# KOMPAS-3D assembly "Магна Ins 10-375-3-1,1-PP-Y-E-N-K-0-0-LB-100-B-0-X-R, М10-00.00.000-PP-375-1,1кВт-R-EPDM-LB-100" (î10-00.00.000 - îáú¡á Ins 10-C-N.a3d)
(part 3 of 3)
- Part/product: Магна Ins 10-PP-425-0,55кВт  | designation М10-00.00.000-PP-425-0,55кВт
    Материал: Полипропилен  ГОСТ 26996-86 (density 900 kg/m3)
    Масса: 11.5823
  - Component [detail]: Втулка ответная  | designation М10А-00.00.003-01  | pos. 6  | Масса: 0.031838; Раздел спецификации: Детали; Форматы листов документа: A4; Примечание: Заим.; source file: D:\AquaProf\АкваProf 190\3Д модель\..\..\..\Magna\Магна Ins\Магна ins 10\М10-00.00.000\3Д\М10А-00.00.003-01 - Втулка ответная.cdw, D:\AquaProf\АкваProf 190\3Д модель\М10А-00.00.003 - Втулка ответная.m3d
  - Component [detail]: Защитная втулка  | designation М10-00.00.003  | pos. 5  | Масса: 0.0193569; Раздел спецификации: Детали; Форматы листов документа: A4; source file: D:\Magna\Магна Ins\Магна ins 10\М10-00.00.000\3Д\М10-00.00.003 - Защитная втулка.cdw, М10-00.00.003 - Защитная втулка.m3d
  - Component [detail]: Импеллер Магна10  | designation М10-00.00.001  | pos. 3  | Масса: 0.169927; Раздел спецификации: Детали; Форматы листов документа: A3; source file: М10-00.00.001 - Импеллер Магна10.cdw, М10-00.00.001 - Импеллер Магна10.m3d
  - Component [detail]: Крышка  | designation М10-00.00.002  | pos. 4
      Материал: Полипропилен  ГОСТ 26996-86 (density 900 kg/m3)
      Масса: 0.324102
      Раздел спецификации: Детали
      Форматы листов документа: 4xA4
      Примечание: @100~)4xA4
      source file: М10-00.00.002 - Крышка.cdw, М10-00.00.002 - Крышка.m3d
  - Component [assembly]: Вал  | designation М10-00.15.000-0,55кВт-425  | pos. 1
      Материал: Полипропилен  ГОСТ 26996-86 (density 900 kg/m3)
      Масса: 0.580892
      Раздел спецификации: Сборочные единицы
      Форматы листов документа: 2xA3
      Примечание: @100~)2xA3
      source file: М10-00.15.000 - Вал.a3d
  - Component [assembly]: Корпус полипропилен 425 0,55кВт  | designation М10-00.20.000-PP-425-0,55кВт  | pos. 2  | Материал: Полипропилен  ГОСТ 26996-86 (density 900 kg/m3); Масса: 5.21242; Раздел спецификации: Сборочные единицы; Форматы листов документа: 3xA3; Примечание: @100~)3xA3@101~)3xA3
- Part/product: Магна Ins 10-425-3-0,55-PP-Y-E-N-K-0-0-L-0-B-0-X-M  | designation М10-00.00.000-PP-425-0,55кВт-M-EPDM
    Материал: Полипропилен  ГОСТ 26996-86 (density 900 kg/m3)
    Масса: 12.5317
  - Component [assembly]: Корпус полипропилен 425 0,55кВт  / с разъёмной муфтой  | designation М10-00.20.000-PP-425-0,55кВт-M  | pos. 2  | Материал: Полипропилен  ГОСТ 26996-86 (density 900 kg/m3); Масса: 6.1618; Раздел спецификации: Сборочные единицы; Форматы листов документа: 3xA3; Примечание: @100~)3xA3@101~)3xA3
  - Component [assembly]: Вал  | designation М10-00.15.000-0,55кВт-425  | pos. 1
      Материал: Полипропилен  ГОСТ 26996-86 (density 900 kg/m3)
      Масса: 0.580892
      Раздел спецификации: Сборочные единицы
      Форматы листов документа: 2xA3
      Примечание: @100~)2xA3
      source file: М10-00.15.000 - Вал.a3d
  - Component [detail]: Крышка  | designation М10-00.00.002  | pos. 4
      Материал: Полипропилен  ГОСТ 26996-86 (density 900 kg/m3)
      Масса: 0.324102
      Раздел спецификации: Детали
      Форматы листов документа: 4xA4
      Примечание: @100~)4xA4
      source file: М10-00.00.002 - Крышка.cdw, М10-00.00.002 - Крышка.m3d
  - Component [detail]: Импеллер Магна10  | designation М10-00.00.001  | pos. 3  | Масса: 0.169927; Раздел спецификации: Детали; Форматы листов документа: A3; source file: М10-00.00.001 - Импеллер Магна10.cdw, М10-00.00.001 - Импеллер Магна10.m3d
  - Component [detail]: Защитная втулка  | designation М10-00.00.003  | pos. 5  | Масса: 0.0193569; Раздел спецификации: Детали; Форматы листов документа: A4; source file: D:\Magna\Магна Ins\Магна ins 10\М10-00.00.000\3Д\М10-00.00.003 - Защитная втулка.cdw, М10-00.00.003 - Защитная втулка.m3d
  - Component [detail]: Втулка ответная  | designation М10А-00.00.003-01  | pos. 6  | Масса: 0.031838; Раздел спецификации: Детали; Форматы листов документа: A4; Примечание: Заим.; source file: D:\AquaProf\АкваProf 190\3Д модель\..\..\..\Magna\Магна Ins\Магна ins 10\М10-00.00.000\3Д\М10А-00.00.003-01 - Втулка ответная.cdw, D:\AquaProf\АкваProf 190\3Д модель\М10А-00.00.003 - Втулка ответная.m3d
- Part/product: Магна Ins 10-425-3-0,55-PP-Y-E-N-K-0-0-L-0-B-0-X-R  | designation М10-00.00.000-PP-425-0,55кВт-R-EPDM
    Материал: Полипропилен  ГОСТ 26996-86 (density 900 kg/m3)
    Масса: 11.6152
  - Component [assembly]: Корпус полипропилен 425 0,55кВт  / с резьбовым переходником  | designation М10-00.20.000-PP-425-0,55кВт-R  | pos. 2  | Материал: Полипропилен  ГОСТ 26996-86 (density 900 kg/m3); Масса: 5.24529; Раздел спецификации: Сборочные единицы; Форматы листов документа: 3xA3; Примечание: @100~)3xA3@101~)3xA3
  - Component [assembly]: Вал  | designation М10-00.15.000-0,55кВт-425  | pos. 1
      Материал: Полипропилен  ГОСТ 26996-86 (density 900 kg/m3)
      Масса: 0.580892
      Раздел спецификации: Сборочные единицы
      Форматы листов документа: 2xA3
      Примечание: @100~)2xA3
      source file: М10-00.15.000 - Вал.a3d
  - Component [detail]: Крышка  | designation М10-00.00.002  | pos. 4
      Материал: Полипропилен  ГОСТ 26996-86 (density 900 kg/m3)
      Масса: 0.324102
      Раздел спецификации: Детали
      Форматы листов документа: 4xA4
      Примечание: @100~)4xA4
      source file: М10-00.00.002 - Крышка.cdw, М10-00.00.002 - Крышка.m3d
  - Component [detail]: Импеллер Магна10  | designation М10-00.00.001  | pos. 3  | Масса: 0.169927; Раздел спецификации: Детали; Форматы листов документа: A3; source file: М10-00.00.001 - Импеллер Магна10.cdw, М10-00.00.001 - Импеллер Магна10.m3d
  - Component [detail]: Защитная втулка  | designation М10-00.00.003  | pos. 5  | Масса: 0.0193569; Раздел спецификации: Детали; Форматы листов документа: A4; source file: D:\Magna\Магна Ins\Магна ins 10\М10-00.00.000\3Д\М10-00.00.003 - Защитная втулка.cdw, М10-00.00.003 - Защитная втулка.m3d
  - Component [detail]: Втулка ответная  | designation М10А-00.00.003-01  | pos. 6  | Масса: 0.031838; Раздел спецификации: Детали; Форматы листов документа: A4; Примечание: Заим.; source file: D:\AquaProf\АкваProf 190\3Д модель\..\..\..\Magna\Магна Ins\Магна ins 10\М10-00.00.000\3Д\М10А-00.00.003-01 - Втулка ответная.cdw, D:\AquaProf\АкваProf 190\3Д модель\М10А-00.00.003 - Втулка ответная.m3d
- Part/product: Магна Ins 10-375-3-0,75-PP-Y-V-N-K-0-0-L-0-B-0-X-M  | designation М10-00.00.000-PP-375-0,75кВт-M-Viton
    Материал: Полипропилен  ГОСТ 26996-86 (density 900 kg/m3)
    Масса: 15.6408
  - Component [detail]: Заглушка @2~25 FV PPR ф. "FV-Plast"  | qty 4  | pos. 12  | Материал: Полипропилен  ГОСТ 26996-86 (density 900 kg/m3); Масса: 0.0161976; Раздел спецификации: Прочие изделия
  - Component [standard]: Болт М10x1,25-6gx60 (S16) ГОСТ 7798-70  | qty 4  | pos. 8  | Масса: 0.0467; Раздел спецификации: Стандартные изделия; Рассекать на разрезах: no; additional columns: Сталь 12Х18Н10Т ГОСТ 5632-72
  - Component [standard]: Гайка М10x1,25-6H(S16) ГОСТ 5915-70  | qty 4  | pos. 9  | Масса: 0.01022; Раздел спецификации: Стандартные изделия; Рассекать на разрезах: no; additional columns: М10x1,25-6H (S16); Сталь 12Х18Н10Т ГОСТ 5632-72
  - Component [standard]: Шайба 10 ГОСТ 6402-70  | qty 4  | pos. 10  | Масса: 0.00201; Раздел спецификации: Стандартные изделия; Примечание: Нерж.; Рассекать на разрезах: no; additional columns: 10; Без указания материала
  - Component [standard]: Шайба C.10.21 ГОСТ 11371-78  | qty 8  | pos. 11  | Материал: Сталь 12Х18Н10Т ГОСТ 5632-72 (density 1000 kg/m3); Масса: 0.003438; Раздел спецификации: Стандартные изделия; Рассекать на разрезах: no; additional columns: Сталь 12Х18Н10Т ГОСТ 5632-72
  - Component [detail]: Втулка ответная  | designation М10А-00.00.003-01  | pos. 6  | Масса: 0.031838; Раздел спецификации: Детали; Форматы листов документа: A4; Примечание: Заим.; source file: D:\AquaProf\АкваProf 190\3Д модель\..\..\..\Magna\Магна Ins\Магна ins 10\М10-00.00.000\3Д\М10А-00.00.003-01 - Втулка ответная.cdw, D:\AquaProf\АкваProf 190\3Д модель\М10А-00.00.003 - Втулка ответная.m3d
  - Component [detail]: Защитная втулка  | designation М10-00.00.003  | pos. 5  | Масса: 0.0193569; Раздел спецификации: Детали; Форматы листов документа: A4; source file: D:\Magna\Магна Ins\Магна ins 10\М10-00.00.000\3Д\М10-00.00.003 - Защитная втулка.cdw, М10-00.00.003 - Защитная втулка.m3d
  - Component [detail]: Импеллер Магна10  | designation М10-00.00.001  | pos. 3  | Масса: 0.169927; Раздел спецификации: Детали; Форматы листов документа: A3; source file: М10-00.00.001 - Импеллер Магна10.cdw, М10-00.00.001 - Импеллер Магна10.m3d
  - Component [detail]: Крышка  | designation М10-00.00.002  | pos. 4
      Материал: Полипропилен  ГОСТ 26996-86 (density 900 kg/m3)
      Масса: 0.324102
      Раздел спецификации: Детали
      Форматы листов документа: 4xA4
      Примечание: @100~)4xA4
      source file: М10-00.00.002 - Крышка.cdw, М10-00.00.002 - Крышка.m3d
  - Component [assembly]: Вал  | designation М10-00.15.000-0,75кВт-375  | pos. 1
      Материал: Полипропилен  ГОСТ 26996-86 (density 900 kg/m3)
      Масса: 0.807009
      Раздел спецификации: Сборочные единицы
      Форматы листов документа: 2xA3
      Примечание: @100~)2xA3
      source file: М10-00.15.000 - Вал.a3d
  - Component [assembly]: Корпус полипропилен 375 0,75кВт  / с разъёмной муфтой  | designation М10-00.20.000-PP-375-0,75кВт-M  | pos. 2
      Материал: Полипропилен  ГОСТ 26996-86 (density 900 kg/m3)
      Масса: 5.65999
      Раздел спецификации: Сборочные единицы
      Форматы листов документа: 3xA3
      Примечание: @100~)3xA3@101~)3xA3
      source file: М10-00.20.000 - Корпус.a3d
  - Component [detail]: Кольцо уплотнительное плоское 10-18-25  | designation Viton  | pos. 93  | Масса: 0.000562973; Раздел спецификации: Прочие изделия
- Part/product: Магна Ins 10-375-3-0,55-PP-Y-E-N-K-0-0-LB-100-B-0-X-M  | designation М10-00.00.000-PP-375-0,55кВт-M-EPDM-LB-100
    Материал: Полипропилен  ГОСТ 26996-86 (density 900 kg/m3)
    Масса: 12.3778
    source file: Новые чертежи Компас\М10-00.00.000-PP-375-0,55кВт-M-EPDM-LB-100 - Магна Ins 10-375-3-0,55-PP-Y-E-N-K-0-0-LB-100-B-0-X-M.cdw, Новые чертежи Компас\М10-00.00.000-PP-375-0,55кВт-M-EPDM-LB-100 - Магна Ins 10-375-3-0,55-PP-Y-E-N-K-0-0-LB-100-B-0-X-M.spw
  - Component [standard]: Кольцо 125-130-25-1-0 ГОСТ 9833-73  | pos. 15
      Материал: Смесь резиновая ИРП-1068 ТУ 38-1051082-86 (density 1280 kg/m3)
      Масса: 0.00019
      Раздел спецификации: Стандартные изделия
      Примечание: EPDM
      Рассекать на разрезах: no
      additional columns: 125-130-25-1-0
  - Component [standard]: Кольцо 058-064-36-1-0 ГОСТ 9833-73  | pos. 14
      Материал: Смесь резиновая ИРП-1068 ТУ 38-1051082-86 (density 1280 kg/m3)
      Масса: 0.00194
      Раздел спецификации: Стандартные изделия
      Примечание: EPDM
      Рассекать на разрезах: no
      additional columns: 058-064-36-1-0
  - Component [detail]: Всасывающая трубка 75  | designation L=100  | pos. 5
      Материал: Полипропилен  ГОСТ 26996-86 (density 900 kg/m3)
      Масса: 0.190378
      Раздел спецификации: Детали
      Форматы листов документа: 3xA3
      Примечание: @100~)3xA3
      source file: D:\Magna\Магна Ins\Магна ins 11\Магна N\3Д\Магна INS 11\Всасывающая трубка 75.m3d, D:\Magna\Магна Ins\Магна ins 11\Магна N\3Д\Магна INS 11\Чертежи\М11-00.00.004-01 - Крышка.cdw
  - Component [detail]: Втулка ответная  | designation М10А-00.00.003-01  | pos. 9  | Масса: 0.031838; Раздел спецификации: Детали; Форматы листов документа: A4; Примечание: Заим.; source file: D:\AquaProf\АкваProf 190\3Д модель\..\..\..\Magna\Магна Ins\Магна ins 10\М10-00.00.000\3Д\М10А-00.00.003-01 - Втулка ответная.cdw, D:\AquaProf\АкваProf 190\3Д модель\М10А-00.00.003 - Втулка ответная.m3d
  - Component [detail]: Защитная втулка  | designation М10-00.00.003  | pos. 8  | Масса: 0.0193569; Раздел спецификации: Детали; Форматы листов документа: A4; source file: D:\Magna\Магна Ins\Магна ins 10\М10-00.00.000\3Д\М10-00.00.003 - Защитная втулка.cdw, М10-00.00.003 - Защитная втулка.m3d
  - Component [detail]: Импеллер Магна10  | designation М10-00.00.001  | pos. 6  | Масса: 0.169927; Раздел спецификации: Детали; Форматы листов документа: A3; source file: М10-00.00.001 - Импеллер Магна10.cdw, М10-00.00.001 - Импеллер Магна10.m3d
  - Component [detail]: Крышка  | designation М10-00.00.002-01  | pos. 7
      Материал: Полипропилен  ГОСТ 26996-86 (density 900 kg/m3)
      Масса: 0.284697
      Раздел спецификации: Детали
      Форматы листов документа: 4xA4
      Примечание: @100~)4xA4
      source file: М10-00.00.002 - Крышка.cdw, М10-00.00.002 - Крышка.m3d

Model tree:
1. Массив по концентрической сетке:1  (4 pattern instances)
     Шаг 2 = 360
2. Сечение поверхностью:5  (with: Операция вращения:1, Операция без истории:1, Вырезать элемент выдавливания:1, Отверстие:1, Операция выдавливания:1, Элемент выдавливания:5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)  (labels: Операция выдавливания:1; Операция выдавливания:1; Полипропилен  ГОСТ 26996-86; v283_d1)

Referenced files in C:\Users\User\Desktop\Магна 10 для Караби\: М10-00.20.000 - Корпус.a3d, М10-00.20.000 - Корпус.cdw, Электродвигатель АИР 63В2 IM 3081 0,55кВт 3000 об..m3d, М10-00.15.000 - Вал.a3d, М10-00.15.000 - Вал.cdw, М10-00.00.002 - Крышка.m3d, М10-00.00.002 - Крышка.cdw, М10-00.00.001 - Импеллер Магна10.m3d, М10-00.00.001 - Импеллер Магна10.cdw, М10-00.00.003 - Защитная втулка.m3d, М10-00.00.003 - Защитная втулка.cdw, М10А-00.00.003-01 - Втулка ответная.cdw, Заглушка ф20 FV PPR ф. FV-Plast.m3d, Кольцо уплотнительное плоское 10-18-25 ЕPDM.m3d, Электродвигатель 3ф. АИР 71А2 380В 0,75кВт 3000об_мин 3081 DRIVE IEK.m3d, Заглушка ф25 FV PPR ф. FV-Plast.m3d
Referenced files in D:\Magna\Магна Ins\Магна ins 10\М10-00.00.000\3Д\: М10-00.00.003 - Защитная втулка.cdw, М10А-00.00.003-01 - Втулка ответная.cdw, М10-00.00.002 - Крышка.cdw, М10-00.15.000 - Вал.cdw, М10-00.00.001 - Импеллер Магна10.cdw
Referenced files in D:\AquaProf\АкваProf 190\3Д модель\: М10А-00.00.003 - Втулка ответная.m3d
Referenced files in C:\Program Files\ASCON\KOMPAS-3D v18\Libs\PartLib\DATA\VAULT\methods\kompas\3d\: PLib_Washer_1_712.m3d, PLib_Washer_2_712.m3d, PLib_Nut_OST92_900.m3d, PLib_Bolt_1_900.m3d
Referenced files in D:\1 ПКИ 3D\РТИ\Кольца уплотнительные  плоские\: Кольцо уплотнительное плоское 10-18-25 ЕPDM.m3d
Referenced files in D:\AquaProf\АкваProf 190\3Д модель\..\..\..\Magna\Магна Ins\Магна ins 10\М10-00.00.000\3Д\: М10А-00.00.003-01 - Втулка ответная.cdw
Referenced files in D:\Magna\Магна Ins\Магна ins 11\Магна N\3Д\Магна INS 11\: Всасывающая трубка 75.m3d
Referenced files in D:\Magna\Магна Ins\Магна ins 11\Магна N\3Д\Магна INS 11\Чертежи\: М11-00.00.004-01 - Крышка.cdw
Referenced files in C:\Program Files\ASCON\KOMPAS-3D v18\Libs\PARTLib\DATA\vault\Methods\Kompas\3D\: PLib_Ring_9833-73_712.m3d
Referenced files in D:\1 ПКИ 3D\Двигатели\АИР\: Электродвигатель АИР 71B2 IM 3081 1,1кВт 2790 об..m3d, Электродвигатель 3ф. АИР 71А2 380В 0,75кВт 3000об_мин 3081 DRIVE IEK.m3d
Referenced files in D:\1 ПКИ 3D\Полипропиленовые фитинги, трубы\: Заглушка ф25 FV PPR ф. FV-Plast.m3d
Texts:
  Body Specification ( left align )
  Body Specificaton ( centered )
  @100~)3xA3@101~)3xA3
  М10-00.20.000-PP-425-0,75кВт-R
  Электродвигатель АИР 63В2
  IM 3081 0,55кВт 3000 об/мин
  @100~)2xA3
  @100~)4xA4
  Крепежное изделие ГОСТ
  IM 3081 3000 об/мин IP55
  Электродвигатель  / IM 3081 3000 об/мин IP55
  М10-00.15.000 - 0,55кВт-375
  М10-00.20.000 - PP-375-0,55кВт
  М10-00.20.000 - PP-375-0,55кВт-R
  с резьбовым переходником
  М10-00.20.000-PP-375-0,55кВт-R
  М10-00.20.000 - PP-375-0,55кВт-M
  с разъёмной муфтой
  М10-00.20.000-PP-375-0,55кВт-M
  IP55
  М10-00.15.000 - 0,75кВт
  М10-00.20.000 - PP-375-0,75кВт
  Электродвигатель 3ф. АИР 71А2
  380В 0,75кВт 3000 об/мин 3081 DRIVE IEK
  арт.DRV071-A2-000-8-3030
  М10-00.20.000 - PP-375-0,75кВт-M
  М10-00.20.000-PP-375-0,75кВт-M
  М10-00.15.000 - 0,75кВт-375
  М10-00.15.000-0,75кВт-375
  М10-00.20.000 - PP-375-0,75кВт-R
  М10-00.15.000 - 0,55кВт-425
  М10-00.20.000 - PP-425-0,55кВт
  М10-00.20.000 - PP-425-0,55кВт-M
  М10-00.20.000 - PP-425-0,55кВт-R
  АИР 71B2 IM 3081 IP55 ф."Элком"
  М10-00.15.000 - 0,55кВт-475
  М10-00.20.000 - PP-475
  М10-00.20.000 - PP-425-0,75кВт
  М10-00.15.000 - 0,75кВт-425
  М10-00.20.000 - PP-425-1,1кВт
  М10-00.15.000 - 1,1кВт-425
  М10-00.20.000 - PP-425-0,75кВт-M
  М10-00.20.000 - PP-425-0,75кВт-R
  М10-00.20.000 - PP-425-1,1кВт-M
  М10-00.20.000 - PP-425-1,1кВт-R
  М10-00.15.000 - 1,1кВт-375
  М10-00.20.000 - PP-375-1,1кВт-M
  Корпус полипропилен 375 1,1кВт
  М10-00.20.000 - PP-375-1,1кВт-R
  М10-00.15.000 - 0,75кВт-475
  М10-00.20.000 - PP-475-0,75кВт-M
  М10-00.20.000 - PP-475-0,55кВт-M
  Корпус полипропилен 475 0,55кВт
  М10-00.20.000 - PP-475-0,75кВт
  М10-00.20.000 - PP-475-0,55кВт-R
  М10-00.20.000 - PP-475-1,1кВт
  М10-00.15.000 - 1,1кВт-475
  М10-00.20.000 - PP-475-0,75кВт-R
  М10-00.20.000 - PP-475-1,1кВт-M
  М10-00.20.000 - PP-475-1,1кВт-R
  М10-00.15.000-0,55кВт-375
  @100~)3xA3
  Кольцо резиновое уплотнительное
  Точка начала. Х
  Точка начала. Y
  Точка начала. Z
  PP-375
  PP-375-0,55кВт
  PP-375-0,55кВт-R-EPDM
  PP-375-0,55кВт-R-Viton
  PP-375-0,55кВт-M-EPDM
  PP-375-0,55кВт-M-Viton
  PP-375-0,55кВт-M-EPDM-LB-100
  PP-375-0,75кВт
  PP-375-0,75кВт-M-EPDM
  PP-375-0,75кВт-M-Viton
  PP-375-0,75кВт-R-EPDM
  PP-375-1,1кВт
  PP-375-1,1кВт-M-EPDM
  PP-375-1,1кВт-R-EPDM
  PP-375-1,1кВт-R-EPDM-LB-100
  PP-425
  PP-425-0,55кВт
  PP-425-0,55кВт-M-EPDM
  PP-425-0,55кВт-R-EPDM
  PP-425-0,75кВт
  PP-425-0,75кВт-M-EPDM
  PP-425-0,75кВт-R-EPDM
  PP-425-1,1кВт
  PP-425-1,1кВт-M-EPDM
  PP-425-1,1кВт-R-EPDM
  PP-475
  PP-475-0,55кВт
  PP-475-0,55кВт-M
  PP-475-0,55кВт-R
  PP-475-0,75кВт
  PP-475-0,75кВт-M
  PP-475-0,75кВт-R
  PP-475-1,1кВт
  PP-475-1,1кВт-M
  PP-475-1,1кВт-R
  bcut1
  hole1
  hcut1
  hole2
  cut1
  Труба 32 PN10 S=2,9 FV PPR ф. "FV PLAST"
  EPDM Кольцо уплотнительное плоское 10-18-25
  Электродвигатель АИР 63В2 IM 3081 0,55кВт 3000 об/мин
  -L=100 Всасывающая трубка 75
  Viton Кольцо уплотнительное плоское 10-18-25
  Электродвигатель 3ф. АИР 71А2 380В 0,75кВт 3000 об/мин 3081 DRIVE IEK арт.DRV071-A2-000-8-3030

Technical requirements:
  Gost Type A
